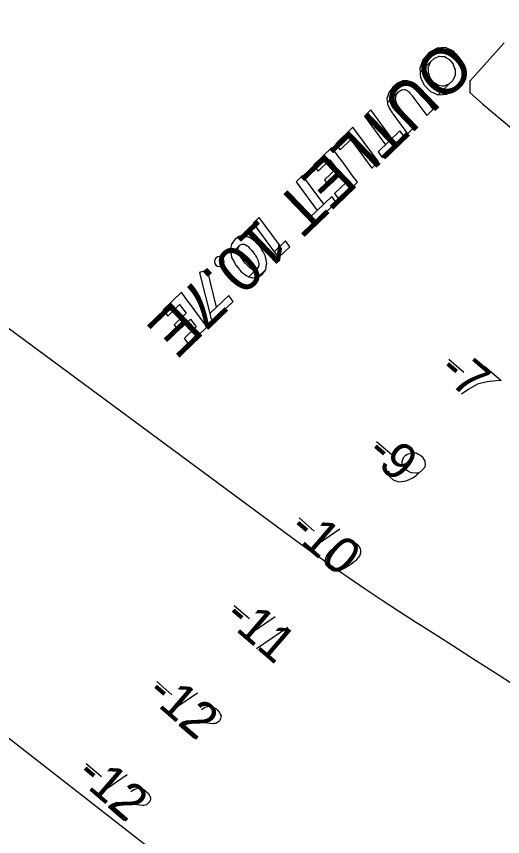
# Model space of a CAD drawing. Extents: x 3962991 to 3983549, y 181631 to 204078.
# Drawn here: x 3972353 to 3972801, y 194775 to 195531 of the extents above; entities that cross this region are included whole.
import ezdxf

# ---------------------------------------------------------------- set-up
doc = ezdxf.new("R2010")
doc.units = 0
for name, color, linetype in [('V-ANNO-MASK', 7, 'Continuous'), ('V-ANNO-MASK2', 7, 'Continuous'), ('V-RIVR-EDGE', 7, 'Continuous'), ('V-RIVR-IDEN', 7, 'Continuous'), ('V-RIVR-RANG', 7, 'Continuous'), ('V-TOPO-DPTH', 7, 'Continuous'), ('V-TOPO-MINR', 7, 'Continuous')]:
    doc.layers.add(name, color=color, linetype=linetype)

msp = doc.modelspace()

# ---------------------------------------------------------------- linework, layer by layer
at = {"layer": 'V-ANNO-MASK2'}
for p, q in [((3972751.88, 195214.99), (3972765.87, 195202.93)), ((3972685.33, 195139.14), (3972699.32, 195127.08)), ((3972613.87, 195068.71), (3972627.86, 195056.66)), ((3972651.49, 195058.23), (3972622.83, 195038.71)), ((3972554.19, 194988.13), (3972568.18, 194976.08)), ((3972591.82, 194977.65), (3972563.16, 194958.12)), ((3972603.41, 194967.66), (3972574.75, 194948.14)), ((3972482.76, 194917.94), (3972496.75, 194905.89)), ((3972520.38, 194907.46), (3972491.72, 194887.94)), ((3972417.82, 194842.56), (3972431.8, 194830.51)), ((3972455.44, 194832.08), (3972426.78, 194812.55))]:
    msp.add_line(p, q, dxfattribs=at)
for points in [[(3972736.46, 195499.04), (3972733.74, 195497.57), (3972727.89, 195490.79), (3972726.89, 195487.85), (3972725.21, 195482.91), (3972725.39, 195479.46), (3972735.06, 195488.77), (3972738.79, 195492.29), (3972743.28, 195494.03), (3972743.4, 195494.03), (3972745.48, 195493.85), (3972745.48, 195493.86), (3972748.11, 195493.63), (3972748.44, 195493.44), (3972749.8, 195492.59), (3972752.38, 195490.96), (3972752.57, 195490.73), (3972752.57, 195490.74), (3972753.02, 195490.18), (3972755.78, 195486.76), (3972755.79, 195486.77), (3972755.83, 195486.7), (3972755.93, 195486.43), (3972757.27, 195482.84), (3972757.73, 195481.62), (3972757.73, 195481.58), (3972757.72, 195478.08), (3972757.72, 195476.47), (3972757.72, 195476.4), (3972755.65, 195471.79), (3972755.64, 195471.76), (3972751.97, 195468.2), (3972741.92, 195458.52), (3972746.42, 195458.76), (3972749.66, 195458.92), (3972754.61, 195461.6), (3972756.83, 195462.8), (3972756.83, 195462.81), (3972762.51, 195469.21), (3972763.73, 195472.47), (3972765.43, 195477.06), (3972765.27, 195481), (3972765.27, 195481.03), (3972765.26, 195481.05), (3972765.16, 195483.56), (3972765.15, 195483.63), (3972765.08, 195485.17), (3972764.02, 195487.64), (3972764.01, 195487.67), (3972763.5, 195488.84), (3972762.01, 195492.28), (3972761.9, 195492.55), (3972761.87, 195492.62), (3972758.86, 195495.8), (3972758.37, 195496.32), (3972758.17, 195496.53), (3972756.13, 195498.69), (3972754.6, 195499.36), (3972754.23, 195499.52), (3972752.27, 195500.39), (3972750.71, 195501.07), (3972750.63, 195501.11), (3972748.78, 195501.91), (3972748.71, 195501.91), (3972744.76, 195501.73), (3972741.14, 195501.56)], [(3972735.01, 195488.65), (3972735.06, 195488.77), (3972725.39, 195479.46), (3972725.4, 195479.39), (3972725.4, 195479.4), (3972725.53, 195476.94), (3972725.53, 195476.82), (3972725.54, 195476.82), (3972725.64, 195474.75), (3972726.54, 195472.86), (3972726.7, 195472.5), (3972726.71, 195472.51), (3972727.4, 195471.02), (3972728.74, 195468.2), (3972728.87, 195467.91), (3972729.19, 195467.23), (3972732.28, 195464.13), (3972732.33, 195464.08), (3972732.52, 195463.89), (3972735, 195461.4), (3972736.2, 195460.89), (3972736.23, 195460.88), (3972738.76, 195459.82), (3972739.92, 195459.33), (3972739.97, 195459.31), (3972741.86, 195458.51), (3972741.88, 195458.52), (3972741.92, 195458.52), (3972751.97, 195468.2), (3972751.91, 195468.18), (3972751.88, 195468.16), (3972747.35, 195466.42), (3972747.23, 195466.37), (3972745.74, 195466.55), (3972742.51, 195466.93), (3972742.48, 195466.94), (3972741.43, 195467.59), (3972738.34, 195469.49), (3972738.17, 195469.7), (3972738.13, 195469.76), (3972735.36, 195473.18), (3972734.91, 195473.73), (3972734.8, 195474.03), (3972733.66, 195477.05), (3972733.06, 195478.63), (3972733.06, 195479.14), (3972733.03, 195481.86), (3972733, 195484.01), (3972733.09, 195484.22)], [(3972704.65, 195469.24), (3972700.25, 195465.48), (3972698.97, 195463.78), (3972696.55, 195460.54), (3972695.91, 195458.44), (3972694.91, 195455.14), (3972695.08, 195453.2), (3972695.24, 195451.26), (3972705.44, 195461.08), (3972708.14, 195462.91), (3972708.19, 195462.91), (3972708.9, 195463), (3972711.08, 195463.26), (3972711.21, 195463.22), (3972711.24, 195463.2), (3972713.78, 195462.19), (3972714.38, 195461.63), (3972714.55, 195461.48), (3972715, 195461.07), (3972716.09, 195460.06), (3972717.23, 195458.7), (3972717.66, 195458.18), (3972718.17, 195457.56), (3972718.25, 195457.46), (3972719.78, 195455.37), (3972720.72, 195454.1), (3972731.48, 195439.49), (3972737.41, 195445.2), (3972726.65, 195459.8), (3972725.7, 195461.06), (3972724.13, 195463.12), (3972724.05, 195463.23), (3972723.56, 195463.86), (3972723.13, 195464.39), (3972722, 195465.75), (3972721.05, 195466.9), (3972720.59, 195467.3), (3972720.42, 195467.44), (3972719.8, 195467.98), (3972717.9, 195469.62), (3972717.87, 195469.63), (3972717.75, 195469.69), (3972716.44, 195470.26), (3972716.01, 195470.44), (3972715.98, 195470.45), (3972715.42, 195470.69), (3972713.92, 195471.35), (3972711.76, 195471.37), (3972709.36, 195471.39), (3972706.43, 195470.05)], [(3972703.49, 195458.42), (3972705.44, 195461.08), (3972695.24, 195451.26), (3972695.3, 195450.54), (3972695.31, 195450.51), (3972695.35, 195449.95), (3972695.92, 195448.66), (3972695.97, 195448.55), (3972695.99, 195448.51), (3972697.06, 195446.08), (3972697.41, 195445.29), (3972697.5, 195445.06), (3972697.85, 195444.57), (3972698.71, 195443.33), (3972698.71, 195443.33), (3972699.73, 195441.86), (3972700.13, 195441.3), (3972700.59, 195440.64), (3972700.66, 195440.53), (3972702.2, 195438.44), (3972703.14, 195437.17), (3972713.91, 195422.57), (3972719.79, 195428.24), (3972709.07, 195442.87), (3972708.13, 195444.15), (3972706.61, 195446.25), (3972706.53, 195446.36), (3972706.06, 195447.01), (3972705.66, 195447.56), (3972704.74, 195449.13), (3972703.97, 195450.46), (3972703.66, 195450.99), (3972703.54, 195451.19), (3972703.34, 195452.13), (3972702.71, 195454.99), (3972702.7, 195455.03), (3972702.75, 195455.23), (3972703.24, 195457.54), (3972703.39, 195458.3)], [(3972699.44, 195418.2), (3972680.01, 195444.53), (3972674.08, 195438.81), (3972693.51, 195412.49)], [(3972667.61, 195422.87), (3972663.42, 195428.55), (3972647.69, 195413.41), (3972651.89, 195407.73), (3972661.69, 195417.17), (3972681.04, 195390.92), (3972686.96, 195396.63)], [(3972710.9, 195419.67), (3972706.78, 195425.27), (3972686.69, 195405.92), (3972690.8, 195400.32)], [(3972648.23, 195404.28), (3972644.07, 195409.92), (3972627.24, 195393.71), (3972631.4, 195388.07), (3972642.36, 195398.63), (3972648.24, 195390.67), (3972637.28, 195380.11), (3972641.34, 195374.61), (3972652.31, 195385.17), (3972657.6, 195377.98), (3972646.63, 195367.42), (3972650.78, 195361.79), (3972667.62, 195378), (3972663.47, 195383.63), (3972658.17, 195390.81), (3972654.11, 195396.32)], [(3972636.59, 195357.69), (3972617.16, 195384.01), (3972611.23, 195378.3), (3972630.66, 195351.97)], [(3972648.05, 195359.16), (3972643.94, 195364.76), (3972623.84, 195345.41), (3972627.95, 195339.81)], [(3972596.48, 195319.23), (3972577.13, 195345.47), (3972571.56, 195340.1), (3972590.91, 195313.86)], [(3972558.5, 195327.83), (3972554.66, 195325.27), (3972552.21, 195321.77), (3972551.52, 195320.79), (3972550.77, 195316.72), (3972550.47, 195315.08), (3972551.07, 195312.06), (3972559.33, 195320.01), (3972560.63, 195320.63), (3972561.46, 195321.01), (3972562.07, 195320.94), (3972562.08, 195320.94), (3972563.35, 195320.77), (3972563.76, 195320.72), (3972564.07, 195320.52), (3972566.59, 195318.93), (3972566.86, 195318.67), (3972568.16, 195317.35), (3972568.17, 195317.35), (3972569.69, 195315.81), (3972569.84, 195315.62), (3972570.36, 195314.95), (3972570.36, 195314.96), (3972572.86, 195311.78), (3972573.14, 195311.31), (3972573.54, 195310.65), (3972574.57, 195308.89), (3972575.62, 195307.11), (3972575.79, 195306.58), (3972576.65, 195303.88), (3972576.84, 195303.28), (3972576.71, 195301.45), (3972576.66, 195300.63), (3972576.63, 195300.23), (3972575.22, 195298.33), (3972567.55, 195290.94), (3972570.57, 195290), (3972571.25, 195289.78), (3972575.86, 195290.45), (3972583.15, 195297.47), (3972584.01, 195302.08), (3972584.21, 195303.13), (3972583.55, 195306.35), (3972583.46, 195306.81), (3972583.4, 195307.12), (3972583.27, 195307.76), (3972582.98, 195309.19), (3972582.84, 195309.84), (3972581.59, 195312.16), (3972581.35, 195312.62), (3972580.35, 195314.46), (3972579.38, 195316.27), (3972579.01, 195316.96), (3972578.66, 195317.36), (3972576.04, 195320.43), (3972575.49, 195321.06), (3972575.34, 195321.25), (3972573.92, 195322.89), (3972572.41, 195324.02), (3972572.11, 195324.24), (3972569.74, 195325.98), (3972569.45, 195326.2), (3972569.19, 195326.39), (3972568.37, 195327), (3972567.84, 195327.16), (3972567.52, 195327.26), (3972567.02, 195327.41), (3972564.17, 195328.28), (3972563.11, 195328.6), (3972558.9, 195327.9)], [(3972605.32, 195318.55), (3972601.36, 195323.92), (3972590.91, 195313.86), (3972594.87, 195308.48)], [(3972558.01, 195318.1), (3972559.33, 195320.01), (3972551.08, 195312.06), (3972551.18, 195311.52), (3972551.25, 195311.18), (3972551.36, 195310.62), (3972551.59, 195309.45), (3972551.6, 195309.45), (3972551.66, 195309.08), (3972551.75, 195308.66), (3972553.16, 195306), (3972553.35, 195305.66), (3972554.25, 195303.95), (3972555.31, 195301.96), (3972555.42, 195301.74), (3972555.97, 195301.1), (3972558.56, 195298.01), (3972558.9, 195297.6), (3972559.39, 195297.03), (3972560.67, 195295.5), (3972562.3, 195294.28), (3972562.71, 195293.98), (3972564.77, 195292.44), (3972565.23, 195292.1), (3972566.23, 195291.35), (3972566.83, 195291.16), (3972567.12, 195291.07), (3972567.55, 195290.94), (3972575.22, 195298.33), (3972574.1, 195297.8), (3972573.34, 195297.43), (3972572.62, 195297.5), (3972571.01, 195297.66), (3972570.51, 195297.97), (3972568.26, 195299.33), (3972567.91, 195299.68), (3972566.47, 195301.09), (3972565.06, 195302.49), (3972564.58, 195303.07), (3972564.25, 195303.49), (3972561.7, 195306.62), (3972561.26, 195307.36), (3972561.13, 195307.57), (3972559.99, 195309.48), (3972559.01, 195311.11), (3972558.89, 195311.51), (3972557.95, 195314.64), (3972557.84, 195315.02), (3972557.73, 195315.36), (3972557.89, 195316.91), (3972557.97, 195317.65)], [(3972538.75, 195309.09), (3972537.24, 195308.12), (3972536.2, 195306.64), (3972535.83, 195304.87), (3972536.14, 195303.12), (3972537.11, 195301.62), (3972538.59, 195300.58), (3972540.33, 195300.21), (3972542.08, 195300.53), (3972543.6, 195301.5), (3972544.63, 195302.99), (3972545.02, 195304.73), (3972544.71, 195306.48), (3972543.74, 195308), (3972542.27, 195309.02), (3972540.53, 195309.39)], [(3972529.58, 195297.05), (3972522.15, 195294.75), (3972523.13, 195290.84), (3972531.59, 195256.88), (3972537.86, 195262.92)], [(3972582.87, 195297.07), (3972583.15, 195297.46), (3972575.86, 195290.45), (3972576.01, 195290.47), (3972580.14, 195293.24)], [(3972509.7, 195270.9), (3972505.54, 195276.54), (3972488.71, 195260.33), (3972492.87, 195254.69), (3972503.83, 195265.24), (3972509.71, 195257.28), (3972498.75, 195246.73), (3972502.81, 195241.22), (3972513.77, 195251.78), (3972519.07, 195244.6), (3972508.1, 195234.04), (3972512.25, 195228.41), (3972529.09, 195244.61), (3972524.93, 195250.25), (3972519.64, 195257.43), (3972515.58, 195262.93)], [(3972551.27, 195270.63), (3972549.02, 195273.67), (3972531.59, 195256.88), (3972532.63, 195252.69), (3972534.41, 195250.27), (3972553.04, 195268.21)]]:
    msp.add_lwpolyline(points, close=True, dxfattribs=at)
for points in [[(3972784.71, 195208.64), (3972800.1, 195195.38), (3972798.24, 195195.24), (3972787.1, 195194.04), (3972778.29, 195191.89), (3972770.21, 195187.36), (3972763.44, 195182.74)], [(3972696.71, 195111.93), (3972696.41, 195108.35), (3972697.69, 195106.2), (3972700.49, 195103.79), (3972703.18, 195102.87), (3972704.72, 195102.24), (3972706.24, 195101.97), (3972712.53, 195102.82), (3972718.86, 195105.72), (3972721.7, 195107.8), (3972727.49, 195112.91), (3972730.08, 195115.9), (3972730.31, 195117.79), (3972730.09, 195120.77), (3972729.83, 195121.68), (3972728.35, 195124.01), (3972725.76, 195126.24), (3972723.41, 195127.57), (3972721.67, 195128.37), (3972718.29, 195128.49), (3972713.54, 195127.02), (3972711.22, 195125.54), (3972709.84, 195123.94), (3972708.6, 195120.48), (3972708.54, 195118.79), (3972709.25, 195116.79), (3972711.13, 195114.12), (3972712.93, 195112.57), (3972715.65, 195111.28), (3972717.56, 195110.67), (3972721.34, 195110.2), (3972723.4, 195110.17), (3972724.51, 195110.25)], [(3972668.28, 195043.77), (3972667.88, 195044.11), (3972666.51, 195044.94), (3972665.54, 195045.43), (3972664.76, 195045.75), (3972663.42, 195046.21), (3972661.71, 195046.65), (3972660.19, 195046.91), (3972658.5, 195046.97), (3972657.21, 195046.69), (3972655.75, 195046.2), (3972654.29, 195045.72), (3972652.66, 195045.04), (3972651.57, 195044.58), (3972650.14, 195043.73), (3972647.82, 195042.25), (3972644.64, 195039.77), (3972642.17, 195037.71), (3972640.28, 195035.51), (3972639.1, 195033.74), (3972638.35, 195031.26), (3972638.09, 195029.74), (3972638.05, 195027.68), (3972638.56, 195025.85), (3972638.99, 195025.13), (3972640.02, 195023.9), (3972641.02, 195023.04), (3972642.79, 195021.86), (3972644.53, 195021.05), (3972646.05, 195020.79), (3972648.31, 195020.59), (3972649.42, 195020.67), (3972650.91, 195020.78), (3972652.2, 195021.06), (3972653.11, 195021.32), (3972654.37, 195021.97), (3972654.92, 195022.2), (3972656.18, 195022.86), (3972657.61, 195023.71), (3972659.05, 195024.56), (3972659.93, 195025.19), (3972660.65, 195025.62), (3972661.54, 195026.25), (3972663.49, 195027.7), (3972664.55, 195028.53), (3972665.61, 195029.35), (3972667.01, 195030.58), (3972668.76, 195032.21), (3972669.28, 195032.81), (3972669.77, 195033.78), (3972670.26, 195034.75), (3972670.69, 195036.47), (3972670.78, 195037.78), (3972670.7, 195038.9), (3972670.42, 195040.19), (3972669.96, 195041.27), (3972669.53, 195041.99), (3972669.11, 195042.71), (3972668.28, 195043.77)], [(3972523.95, 194892.2), (3972527.16, 194894.31), (3972530.82, 194895.33), (3972533.48, 194894.78), (3972535.8, 194893.83), (3972537.37, 194892.83), (3972538.37, 194891.96), (3972540, 194890.22), (3972540.85, 194888.78), (3972541.28, 194888.07), (3972541.96, 194886.43), (3972541.87, 194885.12), (3972541.58, 194883.97), (3972541.26, 194883.2), (3972540.78, 194882.23), (3972539.92, 194881.23), (3972538.85, 194880.4), (3972538.14, 194879.98), (3972537.05, 194879.52), (3972535.76, 194879.24), (3972534.65, 194879.16), (3972510.88, 194881.88), (3972506.87, 194880.46), (3972503.31, 194877.95), (3972517.5, 194865.72)], [(3972459.01, 194816.82), (3972462.22, 194818.93), (3972465.88, 194819.95), (3972468.54, 194819.4), (3972470.86, 194818.45), (3972472.43, 194817.44), (3972473.43, 194816.58), (3972475.05, 194814.83), (3972475.91, 194813.4), (3972476.33, 194812.68), (3972477.02, 194811.05), (3972476.93, 194809.73), (3972476.64, 194808.59), (3972476.32, 194807.82), (3972475.83, 194806.85), (3972474.97, 194805.85), (3972473.91, 194805.02), (3972473.19, 194804.59), (3972472.11, 194804.14), (3972470.82, 194803.86), (3972469.7, 194803.77), (3972445.93, 194806.5), (3972441.92, 194805.08), (3972438.37, 194802.57), (3972452.56, 194790.34)]]:
    msp.add_lwpolyline(points, dxfattribs=at)
at = {"layer": 'V-RIVR-EDGE'}
msp.add_lwpolyline([(3972802.79, 195506.45), (3972771.4, 195471.17), (3972771.4, 195460.49), (3972783.28, 195449.8), (3972841.45, 195401.13), (3972912.68, 195340.58), (3972930.49, 195338.21), (3972945.92, 195340.58), (3972948.3, 195340.58), (3972949.49, 195331.08), (3972949.49, 195325.15), (3972956.61, 195318.02), (3973020.72, 195255.1), (3973043.28, 195242.04), (3973061.08, 195223.05), (3973144.19, 195157.75), (3973256.97, 195059.21)], dxfattribs=at)
at = {"layer": 'V-TOPO-DPTH'}
for points in [[(3970915.42, 195982.24), (3974192.01, 193426.38), (3974197.36, 193423.2), (3974202.67, 193419.94), (3974207.91, 193416.57), (3974213.1, 193413.12), (3974218.23, 193409.59), (3974223.33, 193406.01), (3974228.38, 193402.37), (3974233.41, 193398.68), (3974258.51, 193380.02), (3974261.8, 193377.53), (3974265.08, 193375), (3974268.31, 193372.43), (3974271.51, 193369.82), (3974442.17, 193228.56)], [(3973036.62, 194769.28), (3972976.28, 194808.78), (3972915.76, 194848), (3972794.8, 194925.77), (3972777.41, 194936.92), (3972760.02, 194948.06), (3972742.61, 194959.17), (3972725.19, 194970.26), (3972722.18, 194972.18), (3972706.31, 194982.38), (3972690.51, 194992.69), (3972674.82, 195003.17), (3972659.21, 195013.76), (3972641.32, 195026.02), (3972634.73, 195030.59), (3972628.16, 195035.21), (3972621.65, 195039.9), (3972615.17, 195044.63), (3971972.69, 195518.99)]]:
    msp.add_lwpolyline(points, dxfattribs=at)
at = {"layer": 'V-TOPO-MINR'}
msp.add_lwpolyline([(3973036.62, 194769.28), (3972976.28, 194808.78), (3972915.76, 194848), (3972794.8, 194925.77), (3972777.41, 194936.92), (3972760.02, 194948.06), (3972742.61, 194959.17), (3972725.19, 194970.26), (3972722.18, 194972.18), (3972706.31, 194982.38), (3972690.51, 194992.69), (3972674.82, 195003.17), (3972659.21, 195013.76), (3972641.32, 195026.02), (3972634.73, 195030.59), (3972628.16, 195035.21), (3972621.65, 195039.9), (3972615.17, 195044.63), (3971972.69, 195518.99)], dxfattribs=at)

# ---------------------------------------------------------------- texts
at = {"layer": 'V-ANNO-MASK'}
for s, height, rotation, p in [('OUTLET 10.7E', 41.9999, 223.91595, (3972748.59, 195510.56)), ('-7', 33.5, 319.25119, (3972740.86, 195202.2)), ('-9', 33.5, 319.25119, (3972674.31, 195126.35)), ('-10', 33.5, 319.25119, (3972602.85, 195055.92)), ('-11', 33.5, 319.25119, (3972543.17, 194975.34)), ('-12', 33.5, 319.25119, (3972471.74, 194905.15)), ('-12', 33.5, 319.25119, (3972406.8, 194829.77))]:
    msp.add_text(s, height=height, rotation=rotation, dxfattribs=at).set_placement(p)
at = {"layer": 'V-RIVR-IDEN'}
msp.add_text('OUTLET 10.7E', height=41.9999, rotation=223.91595, dxfattribs=at).set_placement((3972748.59, 195510.56))
at = {"layer": 'V-RIVR-RANG'}
for s, p in [('-7', (3972740.86, 195202.2)), ('-9', (3972674.31, 195126.35)), ('-10', (3972602.85, 195055.92)), ('-11', (3972543.17, 194975.34)), ('-12', (3972471.74, 194905.15)), ('-12', (3972406.8, 194829.77))]:
    msp.add_text(s, height=33.5, rotation=319.25119, dxfattribs=at).set_placement(p)

doc.saveas('drawing.dxf')
